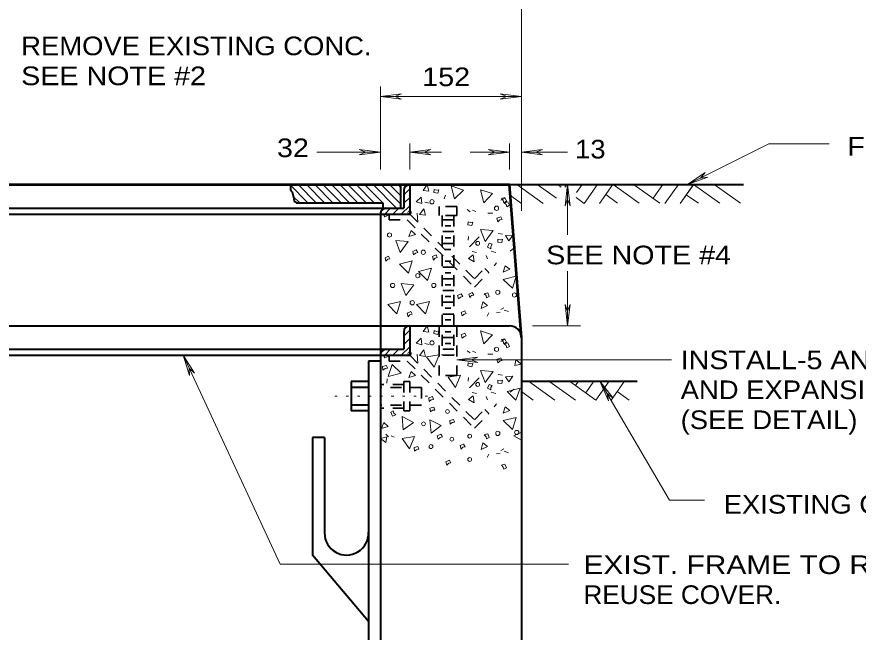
# Model space of a CAD drawing. Extents: x 312583 to 312853, y 144419 to 144586.
# Drawn here: x 312667.1 to 312701.41, y 144475.02 to 144500.1 of the extents above; entities that cross this region are included whole.
import ezdxf

# ---------------------------------------------------------------- set-up
doc = ezdxf.new("R2010")
doc.units = 0
doc.header["$LTSCALE"] = 0.3
doc.header["$PDMODE"] = 32
doc.header["$PDSIZE"] = 0.15
doc.linetypes.add('DOTTED', pattern=[1.5, 0.3, -1.2])
doc.linetypes.add('SHORT_DASHED', pattern=[2.7, 1.5, -1.2])
doc.layers.add('1', color=7, linetype='Continuous', lineweight=40)
doc.layers.add('2', color=7, linetype='Continuous', lineweight=13)

msp = doc.modelspace()

# ---------------------------------------------------------------- linework, layer by layer
at = {"layer": '1', "lineweight": 53}
for p in [(312663.4789, 144493.2596), (312687.6749, 144487.0266)]:
    msp.add_line(p, (312687.1919, 144493.2596), dxfattribs=at)
at = {"layer": '1'}
for p, q in [((312682.7452, 144493.2596), (312682.7452, 144492.3013)), ((312683.1209, 144493.2596), (312683.1209, 144492.0559)), ((312687.1919, 144493.2596), (312696.7292, 144493.2596)), ((312682.8832, 144493.0143), (312682.8832, 144492.3013)), ((312663.4789, 144492.3013), (312682.8832, 144492.3013)), ((312678.4902, 144492.5236), (312682.0245, 144492.5236)), ((312682.0245, 144492.5236), (312682.0245, 144492.3013)), ((312663.3562, 144492.0559), (312683.1209, 144492.0559)), ((312663.4789, 144487.5096), (312687.1919, 144487.5096)), ((312683.1209, 144487.5096), (312683.1209, 144486.3059)), ((312682.8832, 144487.2643), (312682.8832, 144486.5513)), ((312687.6749, 144487.0266), (312687.6749, 144444.3846)), ((312663.7165, 144486.5513), (312682.8832, 144486.5513)), ((312663.4789, 144486.3059), (312683.1209, 144486.3059)), ((312681.9249, 144486.0683), (312681.4419, 144486.0683)), ((312681.4419, 144486.0683), (312681.4419, 144455.4016)), ((312680.7289, 144485.2326), (312680.7289, 144484.0366)), ((312681.4419, 144485.2326), (312680.7289, 144485.2326)), ((312687.6749, 144485.2479), (312692.3975, 144485.2479)), ((312681.4419, 144484.9949), (312680.7289, 144484.9949)), ((312681.4419, 144484.2743), (312680.7289, 144484.2743)), ((312681.4419, 144484.0366), (312680.7289, 144484.0366)), ((312679.1649, 144482.9556), (312679.1649, 144478.1639)), ((312679.6479, 144482.9556), (312679.1649, 144482.9556)), ((312679.6479, 144482.9556), (312679.6479, 144479.0609)), ((312681.4419, 144475.4499), (312679.1649, 144478.1639))]:
    msp.add_line(p, q, dxfattribs=at)
at = {"layer": '1', "linetype": 'SHORT_DASHED', "lineweight": 35}
for p, q in [((312684.3169, 144492.3626), (312684.3169, 144492.0023)), ((312685.0375, 144492.3626), (312684.3169, 144492.3626)), ((312685.0375, 144492.3626), (312685.0375, 144492.0023)), ((312682.2852, 144492.0559), (312682.2852, 144491.8183)), ((312683.1209, 144492.0559), (312685.7582, 144489.4263)), ((312685.0375, 144492.0023), (312684.3169, 144492.0023)), ((312684.4395, 144492.0023), (312684.4395, 144486.3059)), ((312684.9225, 144492.0023), (312684.9225, 144486.3059)), ((312682.2852, 144491.8183), (312683.0212, 144491.8183)), ((312683.0212, 144491.8183), (312685.7582, 144489.0813)), ((312684.9225, 144491.8183), (312684.4395, 144491.8183)), ((312684.7999, 144491.5806), (312684.5622, 144491.5806)), ((312684.9225, 144491.3429), (312684.4395, 144491.3429)), ((312684.9225, 144490.8599), (312684.4395, 144490.8599)), ((312684.7999, 144491.0976), (312684.5622, 144491.0976)), ((312684.7999, 144490.6223), (312684.5622, 144490.6223)), ((312684.9225, 144489.9016), (312684.4395, 144489.9016)), ((312684.7999, 144490.1393), (312684.5622, 144490.1393)), ((312685.7582, 144489.4263), (312686.1799, 144489.8479)), ((312686.1799, 144489.8479), (312686.3485, 144489.6793)), ((312684.7999, 144489.6639), (312684.5622, 144489.6639)), ((312685.7582, 144489.0813), (312686.3485, 144489.6793)), ((312684.9225, 144489.4263), (312684.4395, 144489.4263)), ((312684.7999, 144489.1809), (312684.5622, 144489.1809)), ((312684.9225, 144488.9433), (312684.4395, 144488.9433)), ((312684.9225, 144488.4679), (312684.4395, 144488.4679)), ((312684.7999, 144488.7056), (312684.5622, 144488.7056)), ((312684.7999, 144488.2226), (312684.5622, 144488.2226)), ((312684.9225, 144487.9849), (312684.4395, 144487.9849)), ((312684.3169, 144487.5096), (312684.3169, 144485.4856)), ((312684.9225, 144487.5096), (312684.4395, 144487.5096)), ((312684.7999, 144487.7473), (312684.5622, 144487.7473)), ((312685.0375, 144487.5096), (312685.0375, 144485.4856)), ((312684.7999, 144487.2643), (312684.5622, 144487.2643)), ((312684.9225, 144487.0266), (312684.4395, 144487.0266)), ((312684.7999, 144486.7889), (312684.5622, 144486.7889)), ((312684.9225, 144486.5513), (312684.4395, 144486.5513)), ((312682.2852, 144486.3059), (312682.2852, 144486.0683)), ((312682.2852, 144486.0683), (312683.0212, 144486.0683)), ((312683.0212, 144486.0683), (312685.7582, 144483.3313)), ((312683.1209, 144486.3059), (312685.7582, 144483.6763)), ((312684.9225, 144486.3059), (312684.4395, 144486.3059)), ((312685.0375, 144485.4856), (312684.3169, 144485.4856)), ((312682.8832, 144485.1099), (312681.9249, 144485.1099)), ((312682.8832, 144485.2326), (312682.8832, 144484.0366)), ((312683.1209, 144485.2326), (312682.8832, 144485.2326)), ((312683.1209, 144485.2326), (312683.1209, 144484.0366)), ((312683.6039, 144484.9949), (312681.9249, 144484.9949)), ((312683.6039, 144484.9949), (312683.6039, 144484.2743)), ((312683.6039, 144484.2743), (312681.9249, 144484.2743)), ((312682.8832, 144484.1516), (312681.9249, 144484.1516)), ((312683.1209, 144484.0366), (312682.8832, 144484.0366)), ((312685.7582, 144483.6763), (312686.1799, 144484.0979)), ((312686.1799, 144484.0979), (312686.3485, 144483.9293)), ((312685.7582, 144483.3313), (312686.3485, 144483.9293))]:
    msp.add_line(p, q, dxfattribs=at)
at = {"layer": '1', "linetype": 'DOTTED', "lineweight": 13}
msp.add_line((312680.0695, 144484.6346), (312683.8952, 144484.6346), dxfattribs=at)
at = {"layer": '1'}
for points in [[(312678.2679, 144493.2366), (312678.2679, 144493.0449), (312678.3292, 144492.9606), (312678.3829, 144492.7459), (312678.4135, 144492.5849), (312678.4902, 144492.5389)], [(312681.9249, 144492.0559), (312681.9249, 144486.3059), (312681.9249, 144444.3846)]]:
    msp.add_lwpolyline(points, dxfattribs=at)
for centre, radius, start, end in [((312683.1209, 144493.0171), 0.2396, 90, 180), ((312682.1625, 144492.0588), 0.2396, 90, 180), ((312683.1209, 144487.2671), 0.2396, 90, 180), ((312687.1938, 144487.0276), 0.4792, 0, 90), ((312682.1625, 144486.3088), 0.2396, 90, 180), ((312680.5458, 144479.0614), 0.8984, 180.03057, 1.87136)]:
    msp.add_arc(centre, radius, start, end, dxfattribs=at)
at = {"layer": '2'}
for p, q in [((312687.6749, 144492.1863), (312687.6749, 144501.2329)), ((312681.9249, 144493.8806), (312681.9249, 144497.2616)), ((312681.9249, 144496.8553), (312682.7912, 144496.9626)), ((312681.9249, 144496.8553), (312687.6749, 144496.8553)), ((312681.9249, 144496.8553), (312682.7912, 144496.7479)), ((312682.7912, 144496.9626), (312682.5152, 144496.8553)), ((312682.7912, 144496.7479), (312682.5152, 144496.8553)), ((312686.8085, 144496.9626), (312687.0845, 144496.8553)), ((312687.6749, 144496.8553), (312686.8085, 144496.9626)), ((312686.8085, 144496.7479), (312687.0845, 144496.8553)), ((312687.6749, 144496.8553), (312686.8085, 144496.7479)), ((312681.0585, 144494.6856), (312681.3345, 144494.5783)), ((312681.9249, 144494.5783), (312681.0585, 144494.6856)), ((312683.1209, 144493.8806), (312683.1209, 144494.9309)), ((312683.1209, 144494.5783), (312683.9872, 144494.6856)), ((312683.9872, 144494.6856), (312683.7112, 144494.5783)), ((312686.3255, 144494.6856), (312686.6015, 144494.5783)), ((312687.1919, 144494.5783), (312686.3255, 144494.6856)), ((312687.1919, 144493.8806), (312687.1919, 144494.9309)), ((312687.6749, 144494.5783), (312688.5412, 144494.6856)), ((312688.5412, 144494.6856), (312688.2652, 144494.5783)), ((312694.4522, 144493.2596), (312697.7642, 144494.9233)), ((312700.2175, 144494.9233), (312697.7642, 144494.9233)), ((312679.3412, 144494.5783), (312681.9249, 144494.5783)), ((312681.0585, 144494.4709), (312681.3345, 144494.5783)), ((312681.9249, 144494.5783), (312681.0585, 144494.4709)), ((312683.1209, 144494.5783), (312684.4242, 144494.5783)), ((312683.1209, 144494.5783), (312683.9872, 144494.4709)), ((312683.9872, 144494.4709), (312683.7112, 144494.5783)), ((312685.5895, 144494.5783), (312687.1919, 144494.5783)), ((312686.3255, 144494.4709), (312686.6015, 144494.5783)), ((312687.1919, 144494.5783), (312686.3255, 144494.4709)), ((312687.6749, 144494.5783), (312689.5609, 144494.5783)), ((312687.6749, 144494.5783), (312688.5412, 144494.4709)), ((312688.5412, 144494.4709), (312688.2652, 144494.5783)), ((312694.4522, 144493.2596), (312695.1729, 144493.7503)), ((312695.1729, 144493.7503), (312694.9735, 144493.5203)), ((312695.1729, 144493.7503), (312694.9735, 144493.5203)), ((312678.2372, 144493.2596), (312678.9732, 144492.5236)), ((312678.5745, 144493.2596), (312679.3105, 144492.5236)), ((312678.9119, 144493.2596), (312679.6479, 144492.5236)), ((312679.2492, 144493.2596), (312679.9852, 144492.5236)), ((312679.5865, 144493.2596), (312680.3302, 144492.5236)), ((312679.9315, 144493.2596), (312680.6675, 144492.5236)), ((312680.2689, 144493.2596), (312681.0049, 144492.5236)), ((312680.6062, 144493.2596), (312681.3422, 144492.5236)), ((312680.9435, 144493.2596), (312681.6795, 144492.5236)), ((312681.2809, 144493.2596), (312682.0245, 144492.5236)), ((312681.6259, 144493.2596), (312682.5842, 144492.3013)), ((312681.9632, 144493.2596), (312682.7452, 144492.4776)), ((312682.3005, 144493.2596), (312682.7452, 144492.8149)), ((312682.6379, 144493.2596), (312682.7452, 144493.1523)), ((312688.5565, 144492.4929), (312687.4909, 144493.2596)), ((312687.8972, 144493.2596), (312690.0822, 144493.2596)), ((312689.1469, 144493.2673), (312689.3002, 144493.1599)), ((312689.5225, 144493.2596), (312689.4459, 144493.1523)), ((312689.5609, 144493.2596), (312689.4535, 144492.3933)), ((312689.5609, 144491.2203), (312689.5609, 144493.2596)), ((312689.5609, 144493.2596), (312689.6682, 144492.3933)), ((312690.1512, 144493.2596), (312689.9212, 144492.9376)), ((312690.7799, 144493.2596), (312690.2355, 144492.4929)), ((312691.4009, 144493.2596), (312690.8642, 144492.4929)), ((312692.4819, 144492.5006), (312691.4162, 144493.2673)), ((312693.4479, 144493.2673), (312693.0492, 144492.7076)), ((312694.0765, 144493.2673), (312693.5245, 144492.4929)), ((312694.6899, 144493.2596), (312694.1455, 144492.4929)), ((312694.6899, 144493.2519), (312694.1455, 144492.4853)), ((312694.4522, 144493.2596), (312695.2725, 144493.5586)), ((312695.7632, 144492.5006), (312694.6975, 144493.2596)), ((312695.2725, 144493.5586), (312694.9735, 144493.5203)), ((312695.2725, 144493.5586), (312694.9735, 144493.5203)), ((312682.8832, 144492.8379), (312683.1209, 144493.0833)), ((312689.1009, 144492.7076), (312688.3649, 144493.2366)), ((312693.3252, 144492.5006), (312692.2825, 144493.2443)), ((312696.6065, 144492.5006), (312695.5715, 144493.2366)), ((312678.3829, 144492.7689), (312678.6359, 144492.5236)), ((312682.8832, 144492.5006), (312683.1209, 144492.7383)), ((312684.5239, 144492.6846), (312684.5775, 144492.8303)), ((312687.0079, 144492.7076), (312686.8392, 144492.6233)), ((312687.6825, 144492.4929), (312687.1919, 144492.8379)), ((312689.4535, 144492.3933), (312689.5609, 144492.6693)), ((312689.6682, 144492.3933), (312689.5609, 144492.6693)), ((312690.2355, 144492.4929), (312689.9059, 144492.7306)), ((312691.6002, 144492.5006), (312691.1172, 144492.8533)), ((312694.8892, 144492.5006), (312694.3985, 144492.8456)), ((312682.1012, 144492.0559), (312682.3389, 144492.3013)), ((312682.4385, 144492.0559), (312682.6762, 144492.3013)), ((312682.7759, 144492.0559), (312683.1209, 144492.4009)), ((312683.7342, 144492.5389), (312683.9182, 144492.5006)), ((312685.4669, 144492.2399), (312685.5895, 144492.1556)), ((312685.6815, 144492.2169), (312685.8195, 144492.1709)), ((312683.4505, 144491.7339), (312683.4199, 144492.0943)), ((312686.5095, 144492.1019), (312686.3025, 144492.1019)), ((312686.9005, 144491.2433), (312686.7319, 144491.2663)), ((312685.5129, 144491.1436), (312685.5052, 144490.9979)), ((312685.5589, 144490.7296), (312685.9575, 144491.1359)), ((312685.6739, 144490.5379), (312685.8425, 144490.4919)), ((312686.4482, 144490.5456), (312686.6322, 144490.4996)), ((312687.2225, 144490.5456), (312687.3605, 144490.6759)), ((312686.2949, 144490.2389), (312686.2412, 144490.3769)), ((312686.6552, 144490.0703), (312686.5709, 144489.9476)), ((312689.5609, 144487.5096), (312689.5609, 144489.7329)), ((312686.8315, 144488.1689), (312686.9619, 144488.2379)), ((312687.1535, 144488.0846), (312686.9695, 144488.1459)), ((312689.4535, 144488.3759), (312689.5609, 144488.0999)), ((312689.5609, 144487.5096), (312689.4535, 144488.3759)), ((312689.6682, 144488.3759), (312689.5609, 144488.0999)), ((312689.5609, 144487.5096), (312689.6682, 144488.3759)), ((312686.3485, 144488.0309), (312686.2795, 144487.8929)), ((312686.6629, 144488.0386), (312686.8085, 144488.0616)), ((312688.1272, 144487.5096), (312690.0822, 144487.5096)), ((312682.8832, 144487.0879), (312683.1209, 144487.3333)), ((312682.8832, 144486.7506), (312683.1209, 144486.9883)), ((312683.7342, 144486.7889), (312683.9182, 144486.7506)), ((312687.0079, 144486.9576), (312686.8392, 144486.8733)), ((312682.1012, 144486.3059), (312682.3389, 144486.5513)), ((312682.4385, 144486.3059), (312682.6762, 144486.5513)), ((312682.7759, 144486.3059), (312683.1209, 144486.6509)), ((312685.4669, 144486.4899), (312685.5895, 144486.4056)), ((312685.6815, 144486.4669), (312685.8195, 144486.4209)), ((312673.8825, 144486.3059), (312674.1509, 144485.4779)), ((312673.8825, 144486.3059), (312674.3425, 144485.5699)), ((312683.4505, 144485.9839), (312683.4199, 144486.3443)), ((312685.0375, 144486.1143), (312685.9039, 144486.2216)), ((312685.0375, 144486.1143), (312693.7929, 144486.1143)), ((312685.0375, 144486.1143), (312685.9039, 144486.0069)), ((312685.9039, 144486.2216), (312685.6279, 144486.1143)), ((312685.9039, 144486.0069), (312685.6279, 144486.1143)), ((312686.5095, 144486.3519), (312686.3025, 144486.3519)), ((312674.1509, 144485.4779), (312674.1279, 144485.7769)), ((312674.3425, 144485.5699), (312674.1279, 144485.7769)), ((312685.5129, 144485.3936), (312685.5052, 144485.2479)), ((312685.5589, 144484.9796), (312685.9575, 144485.3859)), ((312686.9005, 144485.4933), (312686.7319, 144485.5163)), ((312682.1855, 144485.1636), (312682.2009, 144485.3399)), ((312689.0395, 144484.4813), (312687.9662, 144485.2479)), ((312689.8829, 144484.4813), (312688.8402, 144485.2249)), ((312690.7109, 144484.4813), (312689.6299, 144485.2556)), ((312689.9979, 144485.2479), (312689.8829, 144485.0716)), ((312690.6265, 144485.2479), (312690.2969, 144484.7803)), ((312691.2552, 144485.2479), (312690.7109, 144484.4813)), ((312690.8795, 144485.2479), (312693.7085, 144480.4026)), ((312690.8795, 144485.2479), (312691.2322, 144484.4506)), ((312690.8795, 144485.2479), (312691.4162, 144484.5579)), ((312691.8839, 144485.2479), (312691.3395, 144484.4813)), ((312685.6739, 144484.7879), (312685.8425, 144484.7419)), ((312686.4482, 144484.7956), (312686.6322, 144484.7496)), ((312687.2225, 144484.7956), (312687.3605, 144484.9259)), ((312688.1579, 144484.4813), (312687.6749, 144484.8263)), ((312691.2322, 144484.4506), (312691.1785, 144484.7419)), ((312691.4162, 144484.5579), (312691.1785, 144484.7419)), ((312692.0679, 144484.4813), (312691.5849, 144484.8263)), ((312686.2949, 144484.4889), (312686.2412, 144484.6269)), ((312686.6552, 144484.3203), (312686.5709, 144484.1976)), ((312682.1549, 144483.0859), (312682.2622, 144482.9863)), ((312682.3619, 144483.0246), (312682.4922, 144482.9633)), ((312686.3485, 144482.2809), (312686.2795, 144482.1429)), ((312686.6629, 144482.2886), (312686.8085, 144482.3116)), ((312686.8315, 144482.4189), (312686.9619, 144482.4879)), ((312687.1535, 144482.3346), (312686.9695, 144482.3959)), ((312693.7085, 144480.4026), (312695.1428, 144480.4026))]:
    msp.add_line(p, q, dxfattribs=at)
for points in [[(312683.6652, 144493.0219), (312683.9029, 144492.9913), (312683.8339, 144493.2596)], [(312684.2095, 144493.0296), (312684.1175, 144493.0603), (312684.1022, 144492.9376), (312684.2632, 144492.9069), (312684.3092, 144493.0449)], [(312684.9455, 144492.6769), (312685.3135, 144493.0373), (312684.8152, 144493.2059)], [(312686.1415, 144492.5236), (312686.5019, 144492.8916), (312686.0035, 144493.0526)], [(312683.3815, 144492.5543), (312683.6192, 144492.4853), (312683.5885, 144492.7536)], [(312686.9389, 144492.6156), (312686.9619, 144492.5236), (312687.0692, 144492.5849), (312687.0002, 144492.7306), (312686.8622, 144492.6923)], [(312687.0539, 144492.4469), (312687.0769, 144492.3549), (312687.1842, 144492.4163), (312687.1229, 144492.5619), (312686.9772, 144492.5236)], [(312683.5195, 144492.0406), (312683.7649, 144492.0099), (312683.6959, 144492.2706)], [(312686.7932, 144491.8183), (312686.8852, 144491.8413), (312686.8315, 144491.9486), (312686.6782, 144491.8873), (312686.7165, 144491.7416)], [(312685.5972, 144491.7109), (312685.5052, 144491.7416), (312685.4899, 144491.6189), (312685.6509, 144491.5883), (312685.6969, 144491.7263)], [(312683.3585, 144491.2279), (312683.1822, 144491.3966), (312683.0825, 144491.1436)], [(312686.5249, 144491.3889), (312686.0112, 144491.4349), (312686.2029, 144490.9443)], [(312687.0309, 144491.1819), (312687.1612, 144490.9749), (312687.3222, 144491.1973)], [(312683.0595, 144490.9366), (312682.5535, 144490.9826), (312682.7375, 144490.4996)], [(312686.4252, 144490.7449), (312686.4789, 144490.8293), (312686.3562, 144490.8676), (312686.2949, 144490.7143), (312686.4252, 144490.6453)], [(312686.8085, 144491.0133), (312686.7165, 144491.0363), (312686.7165, 144490.9136), (312686.8775, 144490.9059), (312686.9082, 144491.0439)], [(312683.3585, 144490.4613), (312683.4505, 144490.4919), (312683.3892, 144490.5993), (312683.2435, 144490.5303), (312683.2819, 144490.3923)], [(312682.2315, 144490.2159), (312682.3159, 144490.2389), (312682.2622, 144490.3463), (312682.1165, 144490.2773), (312682.1549, 144490.1393)], [(312684.1635, 144490.2619), (312684.2479, 144490.2849), (312684.1942, 144490.3923), (312684.0485, 144490.3309), (312684.0869, 144490.1853)], [(312685.7122, 144490.3999), (312685.5129, 144490.2543), (312685.7505, 144490.1163)], [(312682.6992, 144490.0243), (312683.0672, 144489.6563), (312683.2282, 144490.1546)], [(312683.4812, 144489.7253), (312683.8415, 144489.3573), (312684.0102, 144489.8556)], [(312687.1995, 144489.8096), (312687.0079, 144489.9553), (312686.9389, 144489.6946)], [(312686.9389, 144489.3956), (312687.3069, 144489.0353), (312687.4679, 144489.5259)], [(312683.2895, 144489.1809), (312682.7759, 144489.2269), (312682.9675, 144488.7363)], [(312685.1909, 144488.6749), (312685.2829, 144488.7056), (312685.2215, 144488.8129), (312685.0759, 144488.7439), (312685.1142, 144488.6059)], [(312685.6432, 144488.7363), (312685.7352, 144488.7593), (312685.6739, 144488.8666), (312685.5282, 144488.7976), (312685.5665, 144488.6596)], [(312686.2335, 144488.7363), (312686.2565, 144488.6519), (312686.3639, 144488.7056), (312686.3025, 144488.8513), (312686.1569, 144488.8129)], [(312682.2239, 144488.3683), (312682.5919, 144488.0003), (312682.7529, 144488.4986)], [(312683.4045, 144488.3683), (312683.7649, 144488.0003), (312683.9335, 144488.4986)], [(312686.2949, 144488.3376), (312686.1032, 144488.4833), (312686.0342, 144488.2149)], [(312685.3365, 144487.9773), (312685.4285, 144488.0079), (312685.3749, 144488.1153), (312685.2215, 144488.0463), (312685.2675, 144487.9083)], [(312683.1285, 144487.9543), (312683.2205, 144487.9773), (312683.1669, 144488.0846), (312683.0135, 144488.0233), (312683.0595, 144487.8776)], [(312683.6652, 144487.2719), (312683.9029, 144487.2413), (312683.8339, 144487.5096)], [(312684.2095, 144487.2796), (312684.1175, 144487.3103), (312684.1022, 144487.1876), (312684.2632, 144487.1569), (312684.3092, 144487.2949)], [(312685.3365, 144487.0726), (312685.4285, 144487.0956), (312685.3749, 144487.2029), (312685.2215, 144487.1416), (312685.2675, 144486.9959)], [(312686.1415, 144486.7736), (312686.5019, 144487.1416), (312686.0035, 144487.3026)], [(312683.3815, 144486.8043), (312683.6192, 144486.7353), (312683.5885, 144487.0036)], [(312686.9389, 144486.8656), (312686.9619, 144486.7736), (312687.0692, 144486.8349), (312687.0002, 144486.9806), (312686.8622, 144486.9423)], [(312687.0539, 144486.6969), (312687.0769, 144486.6049), (312687.1842, 144486.6663), (312687.1229, 144486.8119), (312686.9772, 144486.7736)], [(312683.5195, 144486.2906), (312683.7649, 144486.2599), (312683.6959, 144486.5206)], [(312684.3169, 144486.3213), (312683.8109, 144486.2369), (312684.1175, 144485.8153)], [(312686.7932, 144486.0683), (312686.8852, 144486.0913), (312686.8315, 144486.1986), (312686.6782, 144486.1373), (312686.7165, 144485.9916)], [(312687.4449, 144486.1219), (312687.4065, 144485.8843), (312687.6749, 144485.9456)], [(312682.1242, 144485.7616), (312682.2162, 144485.7769), (312682.1779, 144485.8919), (312682.0169, 144485.8459), (312682.0322, 144485.7003)], [(312682.7759, 144485.5699), (312682.4079, 144485.9303), (312682.2469, 144485.4396)], [(312685.5972, 144485.9609), (312685.5052, 144485.9916), (312685.4899, 144485.8689), (312685.6509, 144485.8383), (312685.6969, 144485.9763)], [(312683.3585, 144485.4779), (312683.1822, 144485.6466), (312683.0825, 144485.3936)], [(312685.1909, 144485.5009), (312684.6849, 144485.4166), (312684.9915, 144484.9949)], [(312686.5249, 144485.6389), (312686.0112, 144485.6849), (312686.2029, 144485.1943)], [(312687.0309, 144485.4319), (312687.1612, 144485.2249), (312687.3222, 144485.4473)], [(312686.4252, 144484.9949), (312686.4789, 144485.0793), (312686.3562, 144485.1176), (312686.2949, 144484.9643), (312686.4252, 144484.8953)], [(312686.8085, 144485.2633), (312686.7165, 144485.2863), (312686.7165, 144485.1636), (312686.8775, 144485.1559), (312686.9082, 144485.2939)], [(312687.0922, 144484.8339), (312687.4525, 144484.4736), (312687.6212, 144484.9643)], [(312684.0025, 144484.4889), (312684.0945, 144484.5043), (312684.0562, 144484.6193), (312683.8952, 144484.5733), (312683.9182, 144484.4276)], [(312685.7122, 144484.6499), (312685.5129, 144484.5043), (312685.7505, 144484.3663)], [(312682.4769, 144483.9446), (312682.4539, 144484.0366), (312682.3465, 144483.9829), (312682.4155, 144483.8296), (312682.5535, 144483.8756)], [(312684.0485, 144484.0673), (312684.1482, 144484.0749), (312684.1022, 144484.1899), (312683.9489, 144484.1516), (312683.9642, 144484.0059)], [(312687.1995, 144484.0596), (312687.0079, 144484.2053), (312686.9389, 144483.9446)], [(312682.8602, 144483.2623), (312683.2819, 144483.5613), (312682.8142, 144483.8066)], [(312683.9949, 144483.1319), (312684.4089, 144483.4386), (312683.9489, 144483.6763)], [(312684.8535, 144483.5613), (312684.9455, 144483.5766), (312684.9072, 144483.6916), (312684.7539, 144483.6456), (312684.7692, 144483.4999)], [(312686.9389, 144483.6456), (312687.3069, 144483.2853), (312687.4679, 144483.7759)], [(312682.2469, 144483.4003), (312682.0705, 144483.5689), (312681.9709, 144483.3159)], [(312682.1549, 144482.7486), (312682.1855, 144482.9863), (312681.9249, 144482.9173)], [(312683.3202, 144483.0016), (312682.8142, 144482.9173), (312683.1132, 144482.4956)], [(312684.3629, 144482.9556), (312684.4549, 144482.9863), (312684.3935, 144483.0936), (312684.2479, 144483.0246), (312684.2862, 144482.8866)], [(312686.2335, 144482.9863), (312686.2565, 144482.9019), (312686.3639, 144482.9556), (312686.3025, 144483.1013), (312686.1569, 144483.0629)], [(312685.2905, 144482.5569), (312685.3825, 144482.5799), (312685.3212, 144482.6873), (312685.1755, 144482.6259), (312685.2139, 144482.4803)], [(312686.2949, 144482.5876), (312686.1032, 144482.7333), (312686.0342, 144482.4649)], [(312683.3969, 144482.4573), (312683.4965, 144482.4726), (312683.4505, 144482.5876), (312683.2972, 144482.5416), (312683.3125, 144482.3959)], [(312684.7155, 144481.9053), (312684.7999, 144481.9283), (312684.7462, 144482.0356), (312684.6005, 144481.9666), (312684.6389, 144481.8286)], [(312686.9389, 144481.7519), (312686.9619, 144481.6599), (312687.0692, 144481.7136), (312687.0002, 144481.8669), (312686.8622, 144481.8209)]]:
    msp.add_lwpolyline(points, close=True, dxfattribs=at)
for points in [[(312682.0399, 144492.0559), (312682.1012, 144491.9486), (312682.2392, 144492.0099), (312682.1702, 144492.0559)], [(312673.8825, 144486.3059), (312677.8462, 144477.7959), (312689.5915, 144477.7959)], [(312682.0399, 144486.3059), (312682.1012, 144486.1986), (312682.2392, 144486.2599), (312682.1702, 144486.3059)], [(312687.6749, 144483.1703), (312687.3682, 144483.0169), (312687.6749, 144482.8406)]]:
    msp.add_lwpolyline(points, dxfattribs=at)
for centre, radius in [((312684.0301, 144492.5618), 0.0865), ((312686.6622, 144492.2971), 0.0865), ((312682.2984, 144491.2067), 0.0865), ((312685.8945, 144490.8676), 0.0784), ((312683.6784, 144490.5043), 0.0865), ((312683.4522, 144489.5507), 0.0865), ((312682.424, 144489.1492), 0.0865), ((312684.1049, 144489.1492), 0.0865), ((312686.7133, 144488.8712), 0.0865), ((312687.3935, 144488.7634), 0.0865), ((312683.227, 144488.4467), 0.0865), ((312684.0301, 144486.8118), 0.0865), ((312686.6622, 144486.5471), 0.0865), ((312685.8945, 144485.1176), 0.0784), ((312684.665, 144484.0136), 0.0784), ((312683.6865, 144483.5124), 0.0784), ((312684.8403, 144482.8847), 0.0784), ((312685.5677, 144483.0102), 0.0784), ((312686.7133, 144483.1212), 0.0865), ((312687.4845, 144483.1581), 0.0865), ((312683.9874, 144482.5838), 0.0784), ((312685.5677, 144482.0567), 0.0784)]:
    msp.add_circle(centre, radius, dxfattribs=at)
for p in [(312683.1209, 144492.1249), (312683.1209, 144486.3749)]:
    msp.add_point(p, dxfattribs=at)

# ---------------------------------------------------------------- texts
for s, width, p in [('REMOVE EXISTING CONC.', 1.1, (312667.2815, 144498.5333)), ('SEE NOTE #2', 1.15, (312667.2815, 144497.3133)), ('152 ', 1.15, (312683.6334, 144497.2733)), ('32 ', 1.15, (312677.7106, 144494.3796)), ('13 ', 1.1, (312689.8633, 144494.3259)), ('FINISHED GRADE ( SEE NOTE 6 )', 1.15, (312700.9655, 144494.4439)), ('SEE NOTE #4', 1.15, (312688.6848, 144490.0125)), ('INSTALL-5 ANCHOR BOLTS', 1.15, (312694.1685, 144485.7376)), ('AND EXPANSION SHIELDS', 1.1, (312694.1685, 144484.5176)), ('(SEE DETAIL)', 1.1, (312694.1685, 144483.2976)), ('EXISTING GRADE', 1.1, (312695.9239, 144479.852)), ('EXIST. FRAME TO REMAIN-', 1.2, (312690.2049, 144477.3886)), ('REUSE COVER.', 1.05, (312690.2049, 144476.1686))]:
    msp.add_text(s, height=0.76, dxfattribs=dict(at, width=width)).set_placement(p)

doc.saveas('drawing.dxf')
